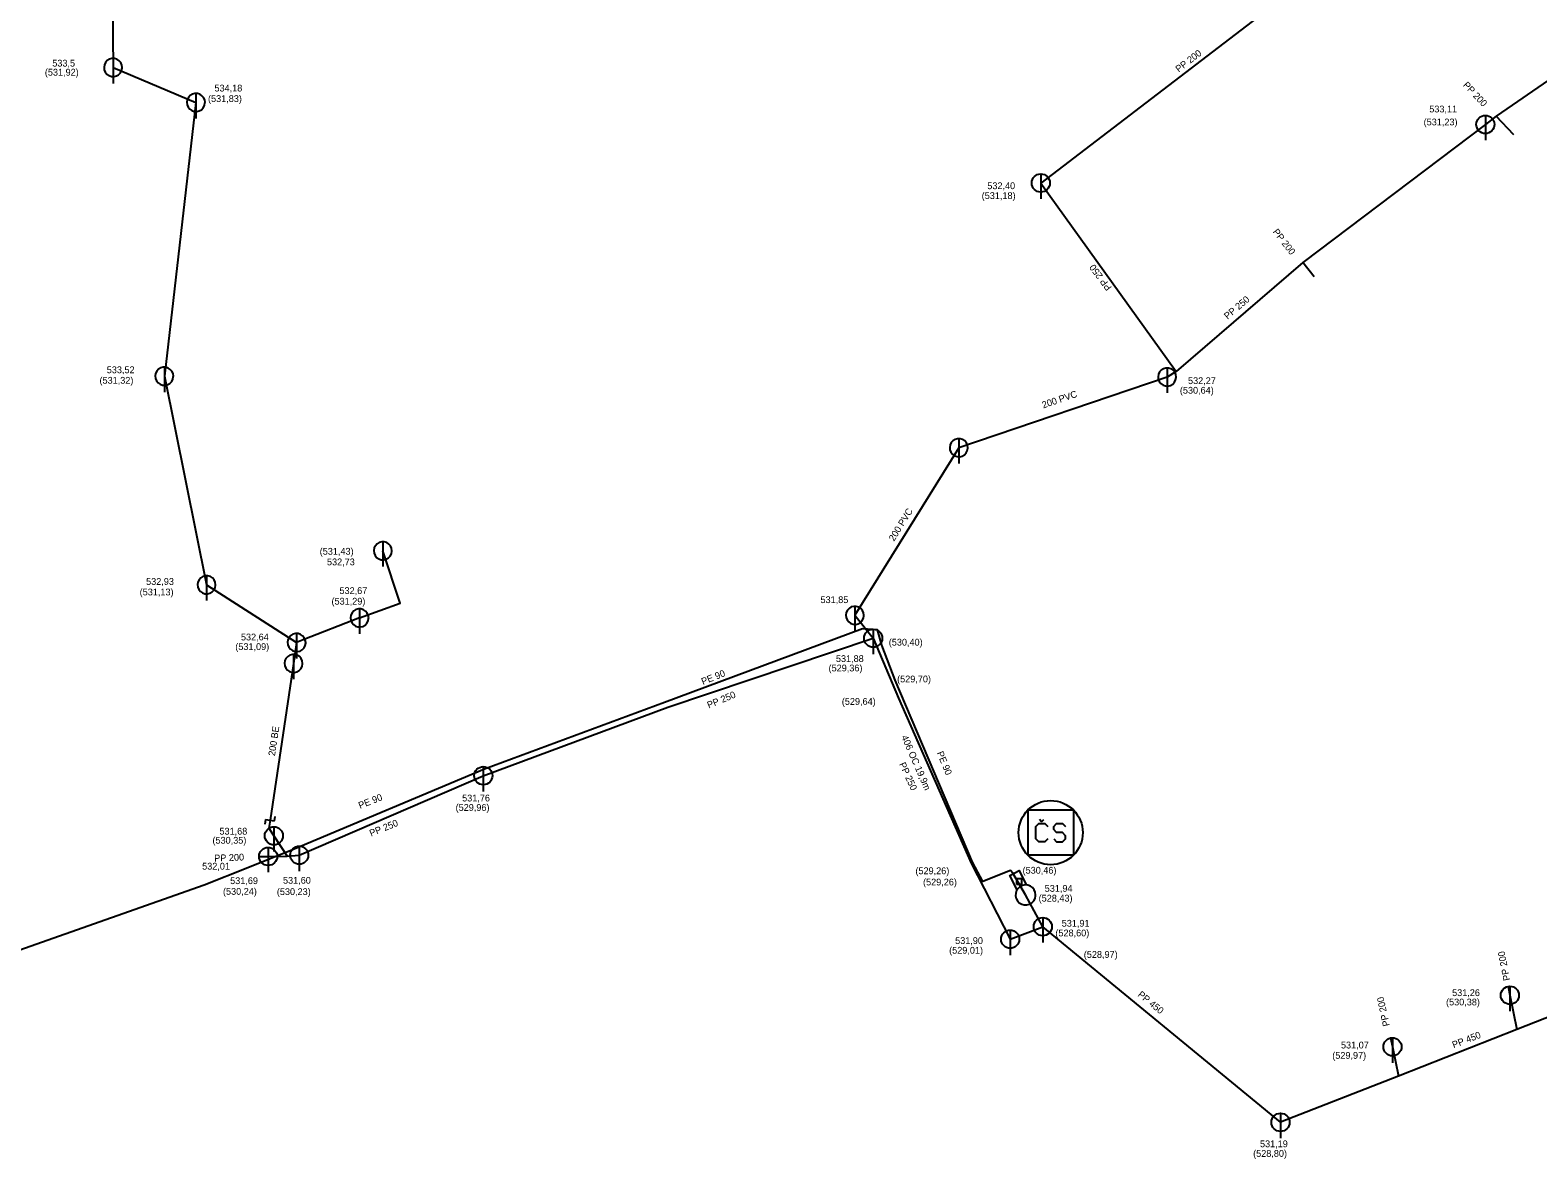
# Model space of a CAD drawing. Extents: x -476058 to -471893, y -1155786 to -1152000.
# Drawn here: x -473097.7 to -472931.4, y -1153849 to -1153724.5 of the extents above; entities that cross this region are included whole.
import ezdxf

# ---------------------------------------------------------------- set-up
doc = ezdxf.new("R2010")
doc.units = 0
for name, color, linetype in [('Vrstva 10', 7, 'Continuous'), ('Vrstva 11', 7, 'Continuous'), ('Vrstva 13', 7, 'Continuous'), ('Vrstva 17', 7, 'Continuous'), ('Vrstva 18', 7, 'Continuous'), ('Vrstva 19', 7, 'Continuous'), ('Vrstva 20', 7, 'Continuous'), ('Vrstva 22', 7, 'Continuous'), ('Vrstva 23', 7, 'Continuous'), ('Vrstva 3', 7, 'Continuous'), ('Vrstva 4', 7, 'Continuous'), ('Vrstva 40', 7, 'Continuous'), ('Vrstva 45', 7, 'Continuous'), ('Vrstva 46', 7, 'Continuous'), ('Vrstva 50', 7, 'Continuous')]:
    doc.layers.add(name, color=color, linetype=linetype)

msp = doc.modelspace()

# ---------------------------------------------------------------- linework, layer by layer
at = {"layer": 'Vrstva 10'}
for p, q in [((-473088.54, -1153727.59), (-473088.54, -1153730.34)), ((-473079.4, -1153731.45), (-473079.4, -1153734.2)), ((-472937.17, -1153733.87), (-472937.17, -1153736.62)), ((-472986.21, -1153740.33), (-472986.21, -1153743.08)), ((-473082.89, -1153761.65), (-473082.89, -1153764.4)), ((-472972.28, -1153761.74), (-472972.28, -1153764.49)), ((-472995.26, -1153769.54), (-472995.26, -1153772.29)), ((-473058.79, -1153780.92), (-473058.79, -1153783.67)), ((-473078.23, -1153784.67), (-473078.23, -1153787.42)), ((-473061.35, -1153788.33), (-473061.35, -1153791.08)), ((-473006.72, -1153788.04), (-473006.72, -1153790.79)), ((-473068.3, -1153791.05), (-473068.3, -1153793.8)), ((-473004.71, -1153790.57), (-473004.71, -1153793.32)), ((-473068.64, -1153793.35), (-473068.64, -1153796.09)), ((-473047.71, -1153805.74), (-473047.71, -1153808.48)), ((-473071.72, -1153811.58), (-473071.79, -1153812.07)), ((-473071.72, -1153811.58), (-473070.73, -1153811.72)), ((-473070.81, -1153812.36), (-473070.81, -1153815.11)), ((-473070.73, -1153811.72), (-473070.65, -1153811.23)), ((-473071.44, -1153814.65), (-473071.44, -1153817.4)), ((-473068.01, -1153814.51), (-473068.01, -1153817.26)), ((-472985.99, -1153822.4), (-472985.99, -1153825.15)), ((-472989.59, -1153823.78), (-472989.59, -1153826.53)), ((-472934.47, -1153829.97), (-472934.47, -1153832.72)), ((-472947.42, -1153835.66), (-472947.42, -1153838.41)), ((-472959.78, -1153843.99), (-472959.78, -1153846.74))]:
    msp.add_line(p, q, dxfattribs=at)
for points in [[(-473087.54, -1153728.59), (-473087.58, -1153728.31), (-473087.7, -1153728.05), (-473087.88, -1153727.84), (-473088.12, -1153727.68), (-473088.39, -1153727.6), (-473088.67, -1153727.6), (-473088.94, -1153727.67), (-473089.18, -1153727.82), (-473089.37, -1153728.03), (-473089.5, -1153728.28), (-473089.54, -1153728.56), (-473089.51, -1153728.84), (-473089.4, -1153729.1), (-473089.23, -1153729.32), (-473088.99, -1153729.48), (-473088.73, -1153729.57), (-473088.44, -1153729.58), (-473088.17, -1153729.52), (-473087.93, -1153729.38), (-473087.73, -1153729.17), (-473087.6, -1153728.92), (-473087.54, -1153728.64), (-473087.54, -1153728.59)], [(-473078.4, -1153732.45), (-473078.44, -1153732.17), (-473078.56, -1153731.91), (-473078.74, -1153731.7), (-473078.98, -1153731.54), (-473079.25, -1153731.46), (-473079.53, -1153731.46), (-473079.8, -1153731.53), (-473080.04, -1153731.68), (-473080.23, -1153731.89), (-473080.36, -1153732.14), (-473080.4, -1153732.42), (-473080.37, -1153732.7), (-473080.26, -1153732.96), (-473080.09, -1153733.18), (-473079.85, -1153733.34), (-473079.59, -1153733.43), (-473079.3, -1153733.44), (-473079.03, -1153733.38), (-473078.79, -1153733.24), (-473078.59, -1153733.03), (-473078.46, -1153732.78), (-473078.41, -1153732.5), (-473078.4, -1153732.45)], [(-473081.89, -1153762.65), (-473081.93, -1153762.37), (-473082.05, -1153762.11), (-473082.23, -1153761.9), (-473082.47, -1153761.75), (-473082.74, -1153761.66), (-473083.02, -1153761.66), (-473083.29, -1153761.73), (-473083.53, -1153761.88), (-473083.72, -1153762.09), (-473083.85, -1153762.34), (-473083.89, -1153762.62), (-473083.86, -1153762.9), (-473083.75, -1153763.16), (-473083.58, -1153763.38), (-473083.34, -1153763.54), (-473083.08, -1153763.63), (-473082.79, -1153763.65), (-473082.52, -1153763.58), (-473082.28, -1153763.44), (-473082.08, -1153763.23), (-473081.95, -1153762.98), (-473081.9, -1153762.71), (-473081.89, -1153762.65)], [(-472971.28, -1153762.74), (-472971.32, -1153762.46), (-472971.44, -1153762.2), (-472971.62, -1153761.99), (-472971.85, -1153761.83), (-472972.12, -1153761.75), (-472972.41, -1153761.75), (-472972.68, -1153761.82), (-472972.92, -1153761.97), (-472973.11, -1153762.18), (-472973.23, -1153762.43), (-472973.28, -1153762.71), (-472973.25, -1153762.99), (-472973.14, -1153763.25), (-472972.96, -1153763.47), (-472972.73, -1153763.63), (-472972.46, -1153763.72), (-472972.18, -1153763.74), (-472971.91, -1153763.67), (-472971.66, -1153763.53), (-472971.47, -1153763.32), (-472971.34, -1153763.07), (-472971.28, -1153762.8), (-472971.28, -1153762.74)], [(-472994.26, -1153770.54), (-472994.3, -1153770.26), (-472994.42, -1153770.01), (-472994.6, -1153769.79), (-472994.84, -1153769.64), (-472995.11, -1153769.55), (-472995.39, -1153769.55), (-472995.66, -1153769.62), (-472995.9, -1153769.77), (-472996.09, -1153769.98), (-472996.21, -1153770.24), (-472996.26, -1153770.51), (-472996.23, -1153770.79), (-472996.12, -1153771.05), (-472995.94, -1153771.27), (-472995.71, -1153771.44), (-472995.44, -1153771.53), (-472995.16, -1153771.54), (-472994.89, -1153771.47), (-472994.64, -1153771.33), (-472994.45, -1153771.12), (-472994.32, -1153770.88), (-472994.26, -1153770.6), (-472994.26, -1153770.54)], [(-473057.79, -1153781.92), (-473057.82, -1153781.64), (-473057.94, -1153781.38), (-473058.12, -1153781.17), (-473058.36, -1153781.01), (-473058.63, -1153780.93), (-473058.91, -1153780.93), (-473059.18, -1153781), (-473059.42, -1153781.15), (-473059.61, -1153781.36), (-473059.74, -1153781.61), (-473059.79, -1153781.89), (-473059.75, -1153782.17), (-473059.64, -1153782.43), (-473059.47, -1153782.65), (-473059.23, -1153782.81), (-473058.97, -1153782.9), (-473058.68, -1153782.91), (-473058.41, -1153782.85), (-473058.17, -1153782.71), (-473057.97, -1153782.5), (-473057.84, -1153782.25), (-473057.79, -1153781.97), (-473057.79, -1153781.92)], [(-473077.23, -1153785.67), (-473077.27, -1153785.39), (-473077.39, -1153785.14), (-473077.57, -1153784.92), (-473077.81, -1153784.77), (-473078.08, -1153784.68), (-473078.36, -1153784.68), (-473078.63, -1153784.76), (-473078.87, -1153784.9), (-473079.06, -1153785.11), (-473079.18, -1153785.37), (-473079.23, -1153785.64), (-473079.2, -1153785.93), (-473079.09, -1153786.19), (-473078.91, -1153786.4), (-473078.68, -1153786.57), (-473078.42, -1153786.66), (-473078.13, -1153786.67), (-473077.86, -1153786.6), (-473077.61, -1153786.46), (-473077.42, -1153786.26), (-473077.29, -1153786.01), (-473077.23, -1153785.73), (-473077.23, -1153785.67)], [(-473060.35, -1153789.33), (-473060.39, -1153789.05), (-473060.51, -1153788.79), (-473060.69, -1153788.58), (-473060.93, -1153788.42), (-473061.2, -1153788.34), (-473061.48, -1153788.34), (-473061.75, -1153788.41), (-473061.99, -1153788.56), (-473062.18, -1153788.77), (-473062.31, -1153789.02), (-473062.35, -1153789.3), (-473062.32, -1153789.58), (-473062.21, -1153789.84), (-473062.04, -1153790.06), (-473061.8, -1153790.22), (-473061.54, -1153790.31), (-473061.26, -1153790.32), (-473060.98, -1153790.26), (-473060.74, -1153790.11), (-473060.54, -1153789.91), (-473060.41, -1153789.66), (-473060.36, -1153789.38), (-473060.35, -1153789.33)], [(-473005.72, -1153789.04), (-473005.76, -1153788.76), (-473005.88, -1153788.5), (-473006.06, -1153788.29), (-473006.29, -1153788.14), (-473006.57, -1153788.05), (-473006.85, -1153788.05), (-473007.12, -1153788.12), (-473007.36, -1153788.27), (-473007.55, -1153788.48), (-473007.67, -1153788.73), (-473007.72, -1153789.01), (-473007.69, -1153789.29), (-473007.58, -1153789.55), (-473007.4, -1153789.77), (-473007.17, -1153789.93), (-473006.9, -1153790.02), (-473006.62, -1153790.04), (-473006.35, -1153789.97), (-473006.1, -1153789.83), (-473005.91, -1153789.62), (-473005.78, -1153789.37), (-473005.72, -1153789.1), (-473005.72, -1153789.04)], [(-473067.3, -1153792.05), (-473067.34, -1153791.77), (-473067.45, -1153791.51), (-473067.64, -1153791.3), (-473067.87, -1153791.14), (-473068.14, -1153791.06), (-473068.42, -1153791.06), (-473068.7, -1153791.13), (-473068.94, -1153791.28), (-473069.13, -1153791.49), (-473069.25, -1153791.74), (-473069.3, -1153792.02), (-473069.27, -1153792.3), (-473069.16, -1153792.56), (-473068.98, -1153792.78), (-473068.75, -1153792.94), (-473068.48, -1153793.03), (-473068.2, -1153793.04), (-473067.92, -1153792.98), (-473067.68, -1153792.84), (-473067.48, -1153792.63), (-473067.35, -1153792.38), (-473067.3, -1153792.1), (-473067.3, -1153792.05)], [(-473067.64, -1153794.35), (-473067.68, -1153794.07), (-473067.8, -1153793.81), (-473067.98, -1153793.59), (-473068.22, -1153793.44), (-473068.49, -1153793.36), (-473068.77, -1153793.35), (-473069.04, -1153793.43), (-473069.28, -1153793.58), (-473069.47, -1153793.79), (-473069.59, -1153794.04), (-473069.64, -1153794.32), (-473069.61, -1153794.6), (-473069.5, -1153794.86), (-473069.32, -1153795.08), (-473069.09, -1153795.24), (-473068.82, -1153795.33), (-473068.54, -1153795.34), (-473068.27, -1153795.27), (-473068.02, -1153795.13), (-473067.83, -1153794.93), (-473067.7, -1153794.68), (-473067.64, -1153794.4), (-473067.64, -1153794.35)]]:
    msp.add_lwpolyline(points, dxfattribs=at)
for centre in [(-472937.17, -1153734.87), (-472986.21, -1153741.33), (-473004.7, -1153791.57), (-473047.71, -1153806.74), (-473070.81, -1153813.37), (-473071.44, -1153815.65), (-473068.01, -1153815.51), (-472985.99, -1153823.4), (-472989.59, -1153824.78), (-472934.47, -1153830.97), (-472947.42, -1153836.66), (-472959.77, -1153844.99)]:
    msp.add_circle(centre, 1, dxfattribs=at)
at = {"layer": 'Vrstva 11'}
for p, q in [((-472987.62, -1153810.52), (-472982.62, -1153810.52)), ((-472987.62, -1153815.52), (-472987.62, -1153810.52)), ((-472982.62, -1153810.52), (-472982.62, -1153815.52)), ((-472982.62, -1153815.52), (-472987.62, -1153815.52))]:
    msp.add_line(p, q, dxfattribs=at)
for points in [[(-472985.45, -1153813.71), (-472985.78, -1153814.02), (-472986.44, -1153814.02), (-472986.75, -1153813.71), (-472986.75, -1153812.34), (-472986.44, -1153812.02), (-472985.78, -1153812.02), (-472985.45, -1153812.34)], [(-472986.12, -1153811.82), (-472986.36, -1153811.58)], [(-472986.12, -1153811.82), (-472985.89, -1153811.58)], [(-472984.78, -1153813.71), (-472984.47, -1153814.02), (-472983.81, -1153814.02), (-472983.48, -1153813.71), (-472983.48, -1153813.38), (-472983.81, -1153813.01), (-472984.47, -1153813.01), (-472984.78, -1153812.67), (-472984.78, -1153812.34), (-472984.47, -1153812.02), (-472983.81, -1153812.02), (-472983.48, -1153812.34)]]:
    msp.add_lwpolyline(points, dxfattribs=at)
msp.add_circle((-472985.12, -1153813.02), 3.54, dxfattribs=at)
at = {"layer": 'Vrstva 13'}
for p, q in [((-472988.3, -1153818.12), (-472988.9, -1153818.12)), ((-472988.9, -1153818.12), (-472988.9, -1153818.72)), ((-472988.9, -1153818.72), (-472988.3, -1153818.72)), ((-472988.3, -1153818.72), (-472988.3, -1153818.12))]:
    msp.add_line(p, q, dxfattribs=at)
at = {"layer": 'Vrstva 22'}
msp.add_lwpolyline([(-472986.78, -1153819.89), (-472986.82, -1153819.6), (-472986.94, -1153819.33), (-472987.12, -1153819.09), (-472987.36, -1153818.92), (-472987.64, -1153818.82), (-472987.94, -1153818.79), (-472988.23, -1153818.84), (-472988.5, -1153818.97), (-472988.72, -1153819.17), (-472988.88, -1153819.42), (-472988.97, -1153819.7), (-472988.99, -1153819.99), (-472988.92, -1153820.28), (-472988.78, -1153820.54), (-472988.58, -1153820.76), (-472988.32, -1153820.91), (-472988.03, -1153820.99), (-472987.74, -1153820.99), (-472987.45, -1153820.91), (-472987.2, -1153820.76), (-472986.99, -1153820.54), (-472986.85, -1153820.28), (-472986.79, -1153819.99), (-472986.78, -1153819.89)], dxfattribs=at)
at = {"layer": 'Vrstva 23'}
for points in [[(-473001.89, -1153798.2), (-472993.89, -1153816.39)], [(-472988.83, -1153819.32), (-472989.64, -1153817.74), (-472988.58, -1153817.19), (-472987.82, -1153818.79)]]:
    msp.add_lwpolyline(points, dxfattribs=at)
at = {"layer": 'Vrstva 40'}
for points in [[(-472929.63, -1153729.59), (-472935.98, -1153733.96)], [(-472935.98, -1153733.96), (-472937.17, -1153734.87)], [(-472937.17, -1153734.87), (-472957.29, -1153750.1)], [(-472957.29, -1153750.1), (-472971.28, -1153762.14)], [(-472971.28, -1153762.14), (-472972.28, -1153762.74)], [(-472959.78, -1153844.99), (-472985.99, -1153823.4)], [(-472919.65, -1153829.24), (-472933.7, -1153834.76)], [(-472933.7, -1153834.76), (-472946.74, -1153839.88)], [(-472946.74, -1153839.88), (-472959.78, -1153844.99)]]:
    msp.add_lwpolyline(points, dxfattribs=at)
at = {"layer": 'Vrstva 45'}
for p, q in [((-473005.87, -1153790.54), (-473027.71, -1153798.67)), ((-473027.35, -1153799.19), (-473004.71, -1153791.57)), ((-472993.73, -1153816.29), (-473002.27, -1153796.21)), ((-473047.71, -1153806.74), (-473027.35, -1153799.19)), ((-473027.71, -1153798.67), (-473047.56, -1153806)), ((-473047.56, -1153806), (-473068.57, -1153814.83)), ((-473068.57, -1153814.83), (-473073.69, -1153816.9)), ((-473073.69, -1153816.9), (-473078.49, -1153818.82)), ((-473078.49, -1153818.82), (-473098.93, -1153826.04))]:
    msp.add_line(p, q, dxfattribs=at)
for points in [[(-473088.92, -1153694.13), (-473088.54, -1153728.59)], [(-473088.54, -1153728.59), (-473079.4, -1153732.45)], [(-473079.4, -1153732.45), (-473082.89, -1153762.65)], [(-473082.89, -1153762.65), (-473078.23, -1153785.67)], [(-473078.23, -1153785.67), (-473068.3, -1153792.05)], [(-473006.72, -1153789.04), (-473004.71, -1153791.57)], [(-473002.27, -1153796.21), (-473003.73, -1153792.32), (-473004.23, -1153790.65), (-473005.87, -1153790.54)], [(-473068.3, -1153792.05), (-473068.64, -1153794.35)], [(-473004.71, -1153791.57), (-473001.89, -1153798.2)], [(-473068.64, -1153794.35), (-473071.22, -1153811.65)], [(-473001.89, -1153798.2), (-472993.89, -1153816.39)], [(-473068.01, -1153815.51), (-473047.71, -1153806.74)], [(-473071.22, -1153811.65), (-473071.35, -1153812.53), (-473070.81, -1153813.36)], [(-473070.81, -1153813.36), (-473069.35, -1153815.61)], [(-473069.35, -1153815.61), (-473068.01, -1153815.51)], [(-472993.89, -1153816.39), (-472989.59, -1153824.78)], [(-472987.89, -1153819.89), (-472989.31, -1153817.49), (-472989.54, -1153817.19), (-472992.59, -1153818.42), (-472993.73, -1153816.29)], [(-472985.99, -1153823.4), (-472987.89, -1153819.89)], [(-472989.59, -1153824.78), (-472985.99, -1153823.4)]]:
    msp.add_lwpolyline(points, dxfattribs=at)
at = {"layer": 'Vrstva 46'}
for points in [[(-472972.28, -1153762.74), (-472995.26, -1153770.54)], [(-472995.26, -1153770.54), (-473006.72, -1153789.04)]]:
    msp.add_lwpolyline(points, dxfattribs=at)
at = {"layer": 'Vrstva 50'}
for points in [[(-472952.58, -1153715.55), (-472986.21, -1153741.33)], [(-472934.05, -1153736.02), (-472935.98, -1153733.96)], [(-472986.21, -1153741.33), (-472971.28, -1153762.14)], [(-472956.06, -1153751.68), (-472957.29, -1153750.1)], [(-473061.35, -1153789.33), (-473056.86, -1153787.71), (-473058.79, -1153781.92)], [(-473061.35, -1153789.33), (-473067.56, -1153791.76), (-473068.3, -1153792.05)], [(-473072.44, -1153815.67), (-473071.44, -1153815.65), (-473069.35, -1153815.61)], [(-472934.66, -1153829.99), (-472934.47, -1153830.97), (-472933.7, -1153834.76)], [(-472947.63, -1153835.68), (-472947.42, -1153836.66), (-472946.74, -1153839.88)]]:
    msp.add_lwpolyline(points, dxfattribs=at)

# ---------------------------------------------------------------- texts
at = {"layer": 'Vrstva 17'}
for s, rotation, p in [('PP 250', 40.2803, (-472965.61, -1153756.42)), ('PP 450', 320.647, (-472975.58, -1153831.01)), ('PP 450', 21.3892, (-472940.66, -1153836.83))]:
    msp.add_text(s, height=0.75, rotation=rotation, dxfattribs=at).set_placement(p)
at = {"layer": 'Vrstva 18'}
for s, rotation, p in [('200 PVC', 18.7522, (-472985.93, -1153766.21)), ('200 PVC', 58.2229, (-473002.4, -1153780.93)), ('PE 90', 21.7861, (-473023.48, -1153796.73)), ('PP 250', 22.4979, (-473022.83, -1153799.33)), ('200 BE', 81.517, (-473070.69, -1153804.6)), ('PE 90', 292.2274, (-472997.7, -1153804.22)), ('PP 250', 294.4688, (-473001.86, -1153805.46)), ('PE 90', 21.7861, (-473061.3, -1153810.41)), ('PP 250', 22.0254, (-473060.08, -1153813.47))]:
    msp.add_text(s, height=0.75, rotation=rotation, dxfattribs=at).set_placement(p)
at = {"layer": 'Vrstva 19'}
for s, rotation, p in [('PP 200', 37.4711, (-472971, -1153729.15)), ('PP 200', 313.0449, (-472939.69, -1153730.57)), ('PP 200', 307.7395, (-472960.67, -1153746.74)), ('PP 250', 126.6536, (-472978.35, -1153752.86)), ('PP 200', 2.3346, (-473077.37, -1153816.22)), ('PP 200', 101.4001, (-472934.42, -1153829.28)), ('PP 200', 102.0242, (-472947.72, -1153834.31))]:
    msp.add_text(s, height=0.75, rotation=rotation, dxfattribs=at).set_placement(p)
at = {"layer": 'Vrstva 20'}
msp.add_text(' 406 OC 19,9m', height=0.75, rotation=293.7349, dxfattribs=at).set_placement((-473001.73, -1153802.21))
at = {"layer": 'Vrstva 3'}
for s, p in [('533,5', (-473095.25, -1153728.48)), ('534,18', (-473077.36, -1153731.23)), ('533,11', (-472943.36, -1153733.54)), ('532,40', (-472992.11, -1153742.01)), ('533,52', (-473089.24, -1153762.32)), ('532,27', (-472969.97, -1153763.52)), ('532,73', (-473064.95, -1153783.52)), ('532,93', (-473084.9, -1153785.68)), ('532,67', (-473063.57, -1153786.69)), ('531,85', (-473010.51, -1153787.69)), ('532,64', (-473074.44, -1153791.81)), ('531,88', (-473008.81, -1153794.19)), ('531,76', (-473050.04, -1153809.58)), ('531,68', (-473076.81, -1153813.24)), ('532,01', (-473078.72, -1153817.1)), ('531,69', (-473075.63, -1153818.7)), ('531,60', (-473069.8, -1153818.66)), ('531,94', (-472985.78, -1153819.55)), ('531,91', (-472983.9, -1153823.4)), ('531,90', (-472995.66, -1153825.31)), ('531,26', (-472940.84, -1153831.06)), ('531,07', (-472953.1, -1153836.84)), ('531,19', (-472962.03, -1153847.74))]:
    msp.add_text(s, height=0.75, dxfattribs=at).set_placement(p)
at = {"layer": 'Vrstva 4'}
for s, p in [('(531,92)', (-473096.07, -1153729.48)), ('(531,83)', (-473078.07, -1153732.39)), ('(531,23)', (-472943.98, -1153734.97)), ('(531,18)', (-472992.73, -1153743.1)), ('(531,32)', (-473090.04, -1153763.48)), ('(530,64)', (-472970.87, -1153764.58)), ('(531,43)', (-473065.75, -1153782.35)), ('(531,13)', (-473085.61, -1153786.84)), ('(531,29)', (-473064.45, -1153787.86)), ('(531,09)', (-473075.06, -1153792.87)), ('(530,40)', (-473002.98, -1153792.38)), ('(529,36)', (-473009.62, -1153795.23)), ('(529,70)', (-473002.06, -1153796.44)), ('(529,64)', (-473008.16, -1153798.92)), ('(529,96)', (-473050.76, -1153810.62)), ('(530,35)', (-473077.58, -1153814.24)), ('(529,26)', (-473000.04, -1153817.61)), ('(530,46)', (-472988.22, -1153817.55)), ('(530,24)', (-473076.42, -1153819.88)), ('(530,23)', (-473070.48, -1153819.91)), ('(529,26)', (-472999.2, -1153818.85)), ('(528,43)', (-472986.45, -1153820.63)), ('(528,60)', (-472984.6, -1153824.47)), ('(529,01)', (-472996.32, -1153826.38)), ('(528,97)', (-472981.47, -1153826.84)), ('(530,38)', (-472941.51, -1153832.09)), ('(529,97)', (-472954.06, -1153837.98)), ('(528,80)', (-472962.79, -1153848.8))]:
    msp.add_text(s, height=0.75, dxfattribs=at).set_placement(p)

doc.saveas('drawing.dxf')
